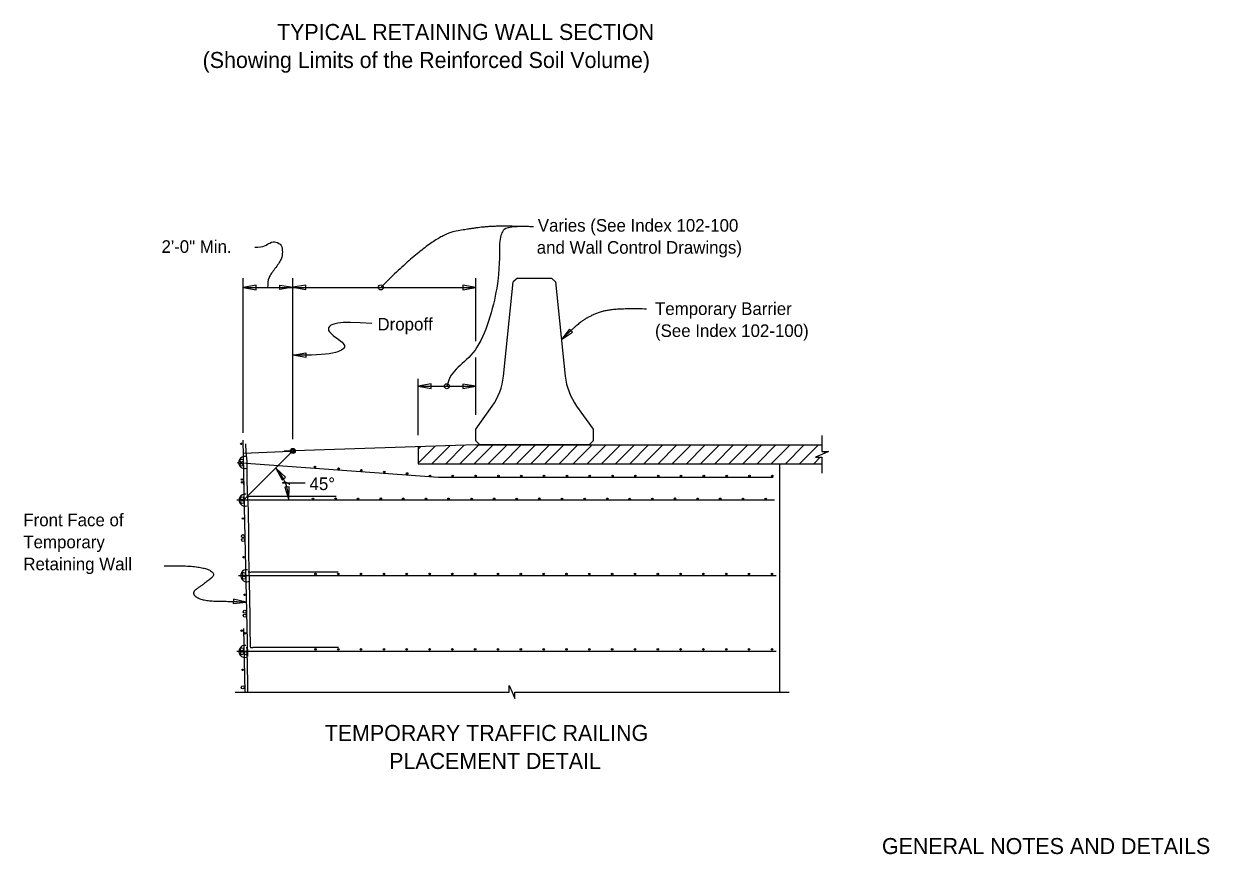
# Model space of a CAD drawing. Extents: x 126777.1 to 126780.68, y 176294.14 to 176295.44.
# Drawn here: x 126779.082 to 126779.674, y 176294.568 to 176294.983 of the extents above; entities that cross this region are included whole.
import ezdxf

# ---------------------------------------------------------------- set-up
doc = ezdxf.new("R2010")
doc.units = 0
for name, color, linetype in [('AdhocPoint_dp', 7, 'Continuous'), ('Border', 7, 'Continuous'), ('Patterning', 7, 'Continuous'), ('SheetBorder_dp', 7, 'Continuous'), ('TextMisc', 7, 'Continuous')]:
    doc.layers.add(name, color=color, linetype=linetype)

# ---------------------------------------------------------------- blocks, each defined once
blk = doc.blocks.new('REBARS')
at = {"layer": 'SheetBorder_dp'}
blk.add_circle((0, 0), 0.000191, dxfattribs=at)

msp = doc.modelspace()

# ---------------------------------------------------------------- linework, layer by layer
at = {"layer": 'AdhocPoint_dp'}
for p, q in [((126779.19148, 176294.77911), (126779.19148, 176294.85639)), ((126779.21634, 176294.7758), (126779.21634, 176294.85639)), ((126779.30777, 176294.8249), (126779.30777, 176294.85639)), ((126779.19148, 176294.8517), (126779.30777, 176294.8517)), ((126779.30777, 176294.78798), (126779.30777, 176294.81659)), ((126779.27893, 176294.77787), (126779.27893, 176294.80595)), ((126779.27893, 176294.80234), (126779.30777, 176294.80234)), ((126779.19192, 176294.74555), (126779.21634, 176294.76997))]:
    msp.add_line(p, q, dxfattribs=at)
for points in [[(126779.19154, 176294.85167), (126779.19805, 176294.85056), (126779.19805, 176294.85277)], [(126779.2163, 176294.85177), (126779.20979, 176294.85067), (126779.20979, 176294.85287)], [(126779.21639, 176294.85177), (126779.2229, 176294.85067), (126779.2229, 176294.85287)], [(126779.30779, 176294.85167), (126779.30129, 176294.85277), (126779.30129, 176294.85056)], [(126779.35066, 176294.82562), (126779.35615, 176294.82928), (126779.35464, 176294.83089)], [(126779.21634, 176294.81782), (126779.22284, 176294.81893), (126779.22284, 176294.81672)], [(126779.27893, 176294.80234), (126779.28543, 176294.80124), (126779.28543, 176294.80344)], [(126779.30779, 176294.8023), (126779.30129, 176294.80341), (126779.30129, 176294.8012)], [(126779.20779, 176294.7613), (126779.21092, 176294.75549), (126779.21266, 176294.75684)], [(126779.21429, 176294.74552), (126779.21447, 176294.75212), (126779.21229, 176294.75181)], [(126779.19305, 176294.69448), (126779.18662, 176294.69593), (126779.1865, 176294.69373)]]:
    msp.add_lwpolyline(points, close=True, dxfattribs=at)
for points in [[(126779.48076, 176294.77771), (126779.48076, 176294.76969), (126779.48399, 176294.76969), (126779.48076, 176294.76828), (126779.47753, 176294.76688), (126779.48076, 176294.76688), (126779.48076, 176294.75885)], [(126779.18753, 176294.64948), (126779.32451, 176294.64948), (126779.32451, 176294.65271), (126779.32592, 176294.64948), (126779.32733, 176294.64625), (126779.32733, 176294.64948), (126779.4643, 176294.64948)]]:
    msp.add_lwpolyline(points, dxfattribs=at)
for centre, radius in [((126779.26029, 176294.8517), 0.00125), ((126779.29335, 176294.80234), 0.00125), ((126779.21632, 176294.76998), 0.00125), ((126779.21632, 176294.76998), 0.000818), ((126779.21632, 176294.76998), 0.00037)]:
    msp.add_circle(centre, radius, dxfattribs=at)
msp.add_arc((126779.19192, 176294.74555), 0.02237, 359.92215, 45, dxfattribs=at)
for points, degree in [([(126779.33653, 176294.88199), (126779.31975, 176294.88245), (126779.3088, 176294.88171), (126779.2862, 176294.87775), (126779.26029, 176294.8517)], 2), ([(126779.33653, 176294.88199), (126779.3228, 176294.88243), (126779.32101, 176294.87972), (126779.31907, 176294.87454), (126779.3203, 176294.85458), (126779.30896, 176294.81456), (126779.29507, 176294.81112), (126779.29335, 176294.80234)], 3), ([(126779.19731, 176294.87172), (126779.20182, 176294.87172), (126779.20517, 176294.87456), (126779.20774, 176294.87456), (126779.21109, 176294.87301), (126779.21109, 176294.86927), (126779.21109, 176294.86618), (126779.20736, 176294.86089), (126779.20389, 176294.85668), (126779.20376, 176294.85354), (126779.20375, 176294.8517)], 3), ([(126779.39315, 176294.84088), (126779.37638, 176294.84134), (126779.36558, 176294.83789), (126779.35868, 176294.83352), (126779.35063, 176294.82565)], 2), ([(126779.25581, 176294.83368), (126779.23849, 176294.83511), (126779.23116, 176294.83156), (126779.23836, 176294.82623), (126779.2441, 176294.82221), (126779.23836, 176294.81841), (126779.22573, 176294.81765), (126779.21634, 176294.81783)], 3), ([(126779.2225, 176294.75384), (126779.21992, 176294.75384), (126779.21377, 176294.75384), (126779.21084, 176294.75384), (126779.21162, 176294.75441), (126779.2125, 176294.75441), (126779.21359, 176294.75418), (126779.21487, 176294.75318)], 2), ([(126779.15195, 176294.71258), (126779.16826, 176294.71293), (126779.17895, 176294.70879), (126779.17102, 176294.70292), (126779.16527, 176294.6989), (126779.17102, 176294.6951), (126779.18349, 176294.69486), (126779.19303, 176294.69453)], 2)]:
    msp.add_open_spline(points, degree=degree, dxfattribs=at)
at = {"layer": 'Border'}
for p, q in [((126779.19134, 176294.77531), (126779.19206, 176294.7426)), ((126779.19149, 176294.7688), (126779.21514, 176294.76995)), ((126779.18858, 176294.76422), (126779.2892, 176294.75688)), ((126779.19175, 176294.75677), (126779.19368, 176294.66719)), ((126779.2892, 176294.75688), (126779.45644, 176294.75688)), ((126779.2892, 176294.75688), (126779.29014, 176294.75688)), ((126779.18842, 176294.74552), (126779.45706, 176294.74552)), ((126779.19123, 176294.74635), (126779.19123, 176294.74635)), ((126779.19123, 176294.74635), (126779.19123, 176294.74635)), ((126779.19123, 176294.74635), (126779.19123, 176294.74635)), ((126779.19123, 176294.74635), (126779.19123, 176294.74635)), ((126779.19123, 176294.74635), (126779.19123, 176294.74635)), ((126779.1954, 176294.74745), (126779.23805, 176294.74745)), ((126779.19165, 176294.7275), (126779.19165, 176294.7275)), ((126779.18925, 176294.70781), (126779.4579, 176294.70781)), ((126779.19206, 176294.70865), (126779.19206, 176294.70865)), ((126779.19206, 176294.70865), (126779.19206, 176294.70865)), ((126779.19634, 176294.70958), (126779.23899, 176294.70958)), ((126779.19248, 176294.68979), (126779.19248, 176294.68979)), ((126779.19165, 176294.68121), (126779.19235, 176294.6495)), ((126779.18837, 176294.66995), (126779.4579, 176294.66995)), ((126779.19113, 176294.67078), (126779.19113, 176294.67078)), ((126779.19649, 176294.67188), (126779.2392, 176294.67188)), ((126779.19154, 176294.65193), (126779.19154, 176294.65193))]:
    msp.add_line(p, q, dxfattribs=at)
for points in [[(126779.19264, 176294.77354), (126779.19285, 176294.76938), (126779.19331, 176294.76495), (126779.19337, 176294.76062), (126779.19342, 176294.75682), (126779.19342, 176294.7538), (126779.19347, 176294.75146), (126779.19347, 176294.74979), (126779.19352, 176294.74865), (126779.19358, 176294.74792), (126779.19363, 176294.74755), (126779.19368, 176294.74734), (126779.19373, 176294.74729), (126779.19389, 176294.74729), (126779.19404, 176294.74729), (126779.19436, 176294.74729), (126779.19488, 176294.74734), (126779.1954, 176294.74745)], [(126779.19358, 176294.7476), (126779.19373, 176294.7463), (126779.19384, 176294.74375), (126779.19394, 176294.74026), (126779.19399, 176294.73615), (126779.1941, 176294.73167), (126779.19415, 176294.72708), (126779.1942, 176294.72276), (126779.19425, 176294.71896), (126779.19425, 176294.71594), (126779.1943, 176294.71365), (126779.19436, 176294.71198), (126779.19436, 176294.71083), (126779.19441, 176294.7101), (126779.19446, 176294.70969), (126779.19451, 176294.70953), (126779.19462, 176294.70948), (126779.19472, 176294.70943), (126779.19493, 176294.70943), (126779.19524, 176294.70948), (126779.19571, 176294.70953), (126779.19634, 176294.70958)], [(126779.1942, 176294.70995), (126779.1943, 176294.70865), (126779.19446, 176294.70609), (126779.19456, 176294.7026), (126779.19462, 176294.69844), (126779.19472, 176294.69396), (126779.19477, 176294.68938), (126779.19483, 176294.68505), (126779.19488, 176294.6813), (126779.19488, 176294.67828), (126779.19493, 176294.67594), (126779.19493, 176294.67427), (126779.19498, 176294.67313), (126779.19503, 176294.6724), (126779.19509, 176294.67203), (126779.19514, 176294.67182), (126779.19524, 176294.67177), (126779.19535, 176294.67177), (126779.1955, 176294.67177), (126779.19581, 176294.67177), (126779.19634, 176294.67182), (126779.19649, 176294.67188)], [(126779.19316, 176294.67189), (126779.19331, 176294.67059), (126779.19342, 176294.66809), (126779.19352, 176294.6646), (126779.19358, 176294.66043), (126779.19368, 176294.65595), (126779.19373, 176294.65137), (126779.19375, 176294.6495)]]:
    msp.add_lwpolyline(points, dxfattribs=at)
for centre in [(126779.19226, 176294.76421), (126779.19248, 176294.74536), (126779.19331, 176294.70764), (126779.1924, 176294.6698)]:
    msp.add_arc(centre, 0.00302, 81.65664, 287.10696, dxfattribs=at)
at = {"layer": 'Patterning'}
for p, q in [((126779.29987, 176294.76358), (126779.30931, 176294.77302)), ((126779.30694, 176294.76358), (126779.31638, 176294.77302)), ((126779.31401, 176294.76358), (126779.32345, 176294.77302)), ((126779.32108, 176294.76358), (126779.33052, 176294.77302)), ((126779.32815, 176294.76358), (126779.33759, 176294.77302)), ((126779.33522, 176294.76358), (126779.34467, 176294.77302)), ((126779.34229, 176294.76358), (126779.35174, 176294.77302)), ((126779.34937, 176294.76358), (126779.35881, 176294.77302)), ((126779.35644, 176294.76358), (126779.36588, 176294.77302)), ((126779.36351, 176294.76358), (126779.37295, 176294.77302)), ((126779.37058, 176294.76358), (126779.38002, 176294.77302)), ((126779.37765, 176294.76358), (126779.38709, 176294.77302)), ((126779.38472, 176294.76358), (126779.39416, 176294.77302)), ((126779.39179, 176294.76358), (126779.40123, 176294.77302)), ((126779.39886, 176294.76358), (126779.40831, 176294.77302)), ((126779.40593, 176294.76358), (126779.41538, 176294.77302)), ((126779.41301, 176294.76358), (126779.42245, 176294.77302)), ((126779.42008, 176294.76358), (126779.42952, 176294.77302)), ((126779.42715, 176294.76358), (126779.43659, 176294.77302)), ((126779.43422, 176294.76358), (126779.44366, 176294.77302)), ((126779.44129, 176294.76358), (126779.45073, 176294.77302)), ((126779.44836, 176294.76358), (126779.4578, 176294.77302)), ((126779.45543, 176294.76358), (126779.46487, 176294.77302)), ((126779.4625, 176294.76358), (126779.47194, 176294.77302)), ((126779.46957, 176294.76358), (126779.47902, 176294.77302)), ((126779.27893, 176294.76385), (126779.28741, 176294.77233)), ((126779.27893, 176294.77092), (126779.28009, 176294.77209)), ((126779.28573, 176294.76358), (126779.29473, 176294.77258)), ((126779.2928, 176294.76358), (126779.30204, 176294.77283)), ((126779.4818, 176294.76873), (126779.48275, 176294.76969)), ((126779.47665, 176294.76358), (126779.47994, 176294.76688))]:
    msp.add_line(p, q, dxfattribs=at)
for centre, start, end in [((126779.28298, 176294.74615), 0, 180), ((126779.28298, 176294.74615), 180, 0), ((126779.33957, 176294.74615), 0, 180), ((126779.33957, 176294.74615), 180, 0), ((126779.40736, 176294.74615), 0, 180), ((126779.40736, 176294.74615), 180, 0)]:
    msp.add_arc(centre, 0.000181, start, end, dxfattribs=at)
at = {"layer": 'SheetBorder_dp'}
for p, q in [((126779.3286, 176294.85639), (126779.32645, 176294.85445)), ((126779.3286, 176294.85639), (126779.34553, 176294.85639)), ((126779.34553, 176294.85639), (126779.34768, 176294.85445)), ((126779.32163, 176294.80734), (126779.32645, 176294.85445)), ((126779.34768, 176294.85445), (126779.3525, 176294.80734)), ((126779.30777, 176294.78087), (126779.31597, 176294.79236)), ((126779.35816, 176294.79236), (126779.36636, 176294.78087)), ((126779.30777, 176294.77501), (126779.30777, 176294.78087)), ((126779.36636, 176294.78087), (126779.36636, 176294.77501)), ((126779.30785, 176294.77302), (126779.21196, 176294.76979)), ((126779.30972, 176294.77306), (126779.30777, 176294.77501)), ((126779.30785, 176294.77302), (126779.48076, 176294.77302)), ((126779.36441, 176294.77306), (126779.30972, 176294.77306)), ((126779.36441, 176294.77306), (126779.36636, 176294.77501)), ((126779.27893, 176294.77205), (126779.27893, 176294.76358)), ((126779.27893, 176294.76358), (126779.48076, 176294.76358)), ((126779.45962, 176294.76356), (126779.45962, 176294.6495))]:
    msp.add_line(p, q, dxfattribs=at)
for centre, start, end in [((126779.29055, 176294.81052), 324.45861, 354.1604), ((126779.38359, 176294.81052), 185.8396, 215.54139)]:
    msp.add_arc(centre, 0.03125, start, end, dxfattribs=at)

# ---------------------------------------------------------------- block references
at = {"layer": 'Border', "rotation": 90}
for p, xscale, yscale in [((126779.19055, 176294.77354), 2.037208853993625, 2.037208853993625), ((126779.19066, 176294.76307), 4.07441770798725, 4.07441770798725), ((126779.19071, 176294.7651), 4.07441770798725, 4.07441770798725), ((126779.22743, 176294.76198), 2.037208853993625, 2.037208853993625), ((126779.2392, 176294.76109), 2.037208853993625, 2.037208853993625), ((126779.19092, 176294.75573), 2.037208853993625, 2.037208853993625), ((126779.25061, 176294.76031), 2.037208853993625, 2.037208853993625), ((126779.26206, 176294.75948), 2.037208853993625, 2.037208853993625), ((126779.27347, 176294.7587), 2.037208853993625, 2.037208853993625), ((126779.28488, 176294.7575), 2.037208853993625, 2.037208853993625), ((126779.29623, 176294.7575), 2.037208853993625, 2.037208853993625), ((126779.30769, 176294.7575), 2.037208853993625, 2.037208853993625), ((126779.3191, 176294.7575), 2.037208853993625, 2.037208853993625), ((126779.3305, 176294.7575), 2.037208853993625, 2.037208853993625), ((126779.34191, 176294.7575), 2.037208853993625, 2.037208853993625), ((126779.35331, 176294.7575), 2.037208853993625, 2.037208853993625), ((126779.36472, 176294.7575), 2.037208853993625, 2.037208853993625), ((126779.37613, 176294.7575), 2.037208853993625, 2.037208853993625), ((126779.38753, 176294.7575), 2.037208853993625, 2.037208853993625), ((126779.39894, 176294.7575), 2.037208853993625, 2.037208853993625), ((126779.41035, 176294.7575), 2.037208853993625, 2.037208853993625), ((126779.42175, 176294.7575), 2.037208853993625, 2.037208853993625), ((126779.43316, 176294.7575), 2.037208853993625, 2.037208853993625), ((126779.44456, 176294.7575), 2.037208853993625, 2.037208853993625), ((126779.45597, 176294.7575), 2.037208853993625, 2.037208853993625), ((126779.19102, 176294.75427), 2.037208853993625, 2.037208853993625), ((126779.19102, 176294.74625), 4.07441770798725, 4.07441770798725), ((126779.19108, 176294.74443), 4.07441770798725, 4.07441770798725), ((126779.22639, 176294.74604), 2.037208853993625, 2.037208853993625), ((126779.23769, 176294.74615), 2.037208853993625, 2.037208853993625), ((126779.24894, 176294.74604), 2.037208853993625, 2.037208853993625), ((126779.26029, 176294.74609), 2.037208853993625, 2.037208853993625), ((126779.27149, 176294.74604), 2.037208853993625, 2.037208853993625), ((126779.28285, 176294.74604), 2.037208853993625, 2.037208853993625), ((126779.29415, 176294.74604), 2.037208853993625, 2.037208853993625), ((126779.30566, 176294.74599), 2.037208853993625, 2.037208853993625), ((126779.31696, 176294.74604), 2.037208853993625, 2.037208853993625), ((126779.32821, 176294.74599), 2.037208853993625, 2.037208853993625), ((126779.33956, 176294.74609), 2.037208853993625, 2.037208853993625), ((126779.35087, 176294.74599), 2.037208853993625, 2.037208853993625), ((126779.36222, 176294.74599), 2.037208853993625, 2.037208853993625), ((126779.37347, 176294.74604), 2.037208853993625, 2.037208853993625), ((126779.38472, 176294.74594), 2.037208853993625, 2.037208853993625), ((126779.39602, 176294.74599), 2.037208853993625, 2.037208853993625), ((126779.40733, 176294.74609), 2.037208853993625, 2.037208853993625), ((126779.41868, 176294.74604), 2.037208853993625, 2.037208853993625), ((126779.42988, 176294.74604), 2.037208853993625, 2.037208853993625), ((126779.44128, 176294.74599), 2.037208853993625, 2.037208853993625), ((126779.45264, 176294.74599), 2.037208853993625, 2.037208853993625), ((126779.19139, 176294.7362), 2.037208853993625, 2.037208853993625), ((126779.19144, 176294.7274), 4.07441770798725, 4.07441770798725), ((126779.19149, 176294.72552), 4.07441770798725, 4.07441770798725), ((126779.1918, 176294.71688), 2.037208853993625, 2.037208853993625), ((126779.19191, 176294.70854), 4.07441770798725, 4.07441770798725), ((126779.22764, 176294.70854), 2.037208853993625, 2.037208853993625), ((126779.23904, 176294.70854), 2.037208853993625, 2.037208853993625), ((126779.25045, 176294.70854), 2.037208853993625, 2.037208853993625), ((126779.26186, 176294.70854), 2.037208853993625, 2.037208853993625), ((126779.27326, 176294.70854), 2.037208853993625, 2.037208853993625), ((126779.28467, 176294.70854), 2.037208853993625, 2.037208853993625), ((126779.29608, 176294.70854), 2.037208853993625, 2.037208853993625), ((126779.30748, 176294.70854), 2.037208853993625, 2.037208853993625), ((126779.31889, 176294.70854), 2.037208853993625, 2.037208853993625), ((126779.33029, 176294.70854), 2.037208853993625, 2.037208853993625), ((126779.3417, 176294.70854), 2.037208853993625, 2.037208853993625), ((126779.35311, 176294.70854), 2.037208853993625, 2.037208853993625), ((126779.36451, 176294.70854), 2.037208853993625, 2.037208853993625), ((126779.37592, 176294.70854), 2.037208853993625, 2.037208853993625), ((126779.38733, 176294.70854), 2.037208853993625, 2.037208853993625), ((126779.39873, 176294.70854), 2.037208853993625, 2.037208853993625), ((126779.41014, 176294.70854), 2.037208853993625, 2.037208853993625), ((126779.42154, 176294.70854), 2.037208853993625, 2.037208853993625), ((126779.43295, 176294.70854), 2.037208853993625, 2.037208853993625), ((126779.44436, 176294.70854), 2.037208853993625, 2.037208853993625), ((126779.45576, 176294.70854), 2.037208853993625, 2.037208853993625), ((126779.19191, 176294.70667), 4.07441770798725, 4.07441770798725), ((126779.19227, 176294.69807), 2.037208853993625, 2.037208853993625), ((126779.19233, 176294.68964), 4.07441770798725, 4.07441770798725), ((126779.19233, 176294.68771), 4.07441770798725, 4.07441770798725), ((126779.19081, 176294.68016), 2.037208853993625, 2.037208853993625), ((126779.19253, 176294.6788), 2.037208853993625, 2.037208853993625), ((126779.19092, 176294.67083), 4.07441770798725, 4.07441770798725), ((126779.19097, 176294.66891), 4.07441770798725, 4.07441770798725), ((126779.19279, 176294.66891), 4.07441770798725, 4.07441770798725), ((126779.22764, 176294.67083), 2.037208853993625, 2.037208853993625), ((126779.23904, 176294.67083), 2.037208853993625, 2.037208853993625), ((126779.2504, 176294.67083), 2.037208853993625, 2.037208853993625), ((126779.26186, 176294.67083), 2.037208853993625, 2.037208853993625), ((126779.27326, 176294.67083), 2.037208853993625, 2.037208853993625), ((126779.28467, 176294.67083), 2.037208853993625, 2.037208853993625), ((126779.29608, 176294.67083), 2.037208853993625, 2.037208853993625), ((126779.30748, 176294.67083), 2.037208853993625, 2.037208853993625), ((126779.31889, 176294.67083), 2.037208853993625, 2.037208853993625), ((126779.33029, 176294.67083), 2.037208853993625, 2.037208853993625), ((126779.3417, 176294.67083), 2.037208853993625, 2.037208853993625), ((126779.35311, 176294.67083), 2.037208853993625, 2.037208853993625), ((126779.36451, 176294.67083), 2.037208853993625, 2.037208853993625), ((126779.37592, 176294.67083), 2.037208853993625, 2.037208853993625), ((126779.38733, 176294.67083), 2.037208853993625, 2.037208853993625), ((126779.39873, 176294.67083), 2.037208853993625, 2.037208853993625), ((126779.41014, 176294.67083), 2.037208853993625, 2.037208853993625), ((126779.42154, 176294.67083), 2.037208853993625, 2.037208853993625), ((126779.43295, 176294.67083), 2.037208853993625, 2.037208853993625), ((126779.44436, 176294.67083), 2.037208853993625, 2.037208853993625), ((126779.45576, 176294.67083), 2.037208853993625, 2.037208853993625), ((126779.19128, 176294.66063), 2.037208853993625, 2.037208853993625), ((126779.19134, 176294.65182), 4.07441770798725, 4.07441770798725)]:
    msp.add_blockref('REBARS', p, dxfattribs=dict(at, xscale=xscale, yscale=yscale))

# ---------------------------------------------------------------- texts
at = {"layer": 'TextMisc'}
for s, height, p in [('TYPICAL RETAINING WALL SECTION', 0.008, (126779.20844, 176294.97533)), ('(Showing Limits of the Reinforced Soil Volume)', 0.008, (126779.17125, 176294.96133)), ('Varies (See Index 102-100', 0.0063, (126779.33876, 176294.87954)), ('2\'-0" Min.', 0.0063, (126779.15072, 176294.86896)), ('and Wall Control Drawings)', 0.0063, (126779.33824, 176294.86854)), ('Temporary Barrier ', 0.0063, (126779.39733, 176294.83792)), ('Dropoff', 0.0063, (126779.25863, 176294.83017)), ('(See Index 102-100)', 0.0063, (126779.39733, 176294.82692)), ('45°', 0.0063, (126779.22467, 176294.75042)), ('Front Face of ', 0.0063, (126779.08164, 176294.73235)), ('Temporary', 0.0063, (126779.08164, 176294.72135)), ('Retaining Wall', 0.0063, (126779.08164, 176294.71035)), ('TEMPORARY TRAFFIC RAILING', 0.008, (126779.23226, 176294.62507)), ('PLACEMENT DETAIL', 0.008, (126779.26447, 176294.61107)), ('GENERAL NOTES AND DETAILS', 0.008, (126779.51076, 176294.56856))]:
    msp.add_text(s, height=height, dxfattribs=at).set_placement(p)

doc.saveas('drawing.dxf')
